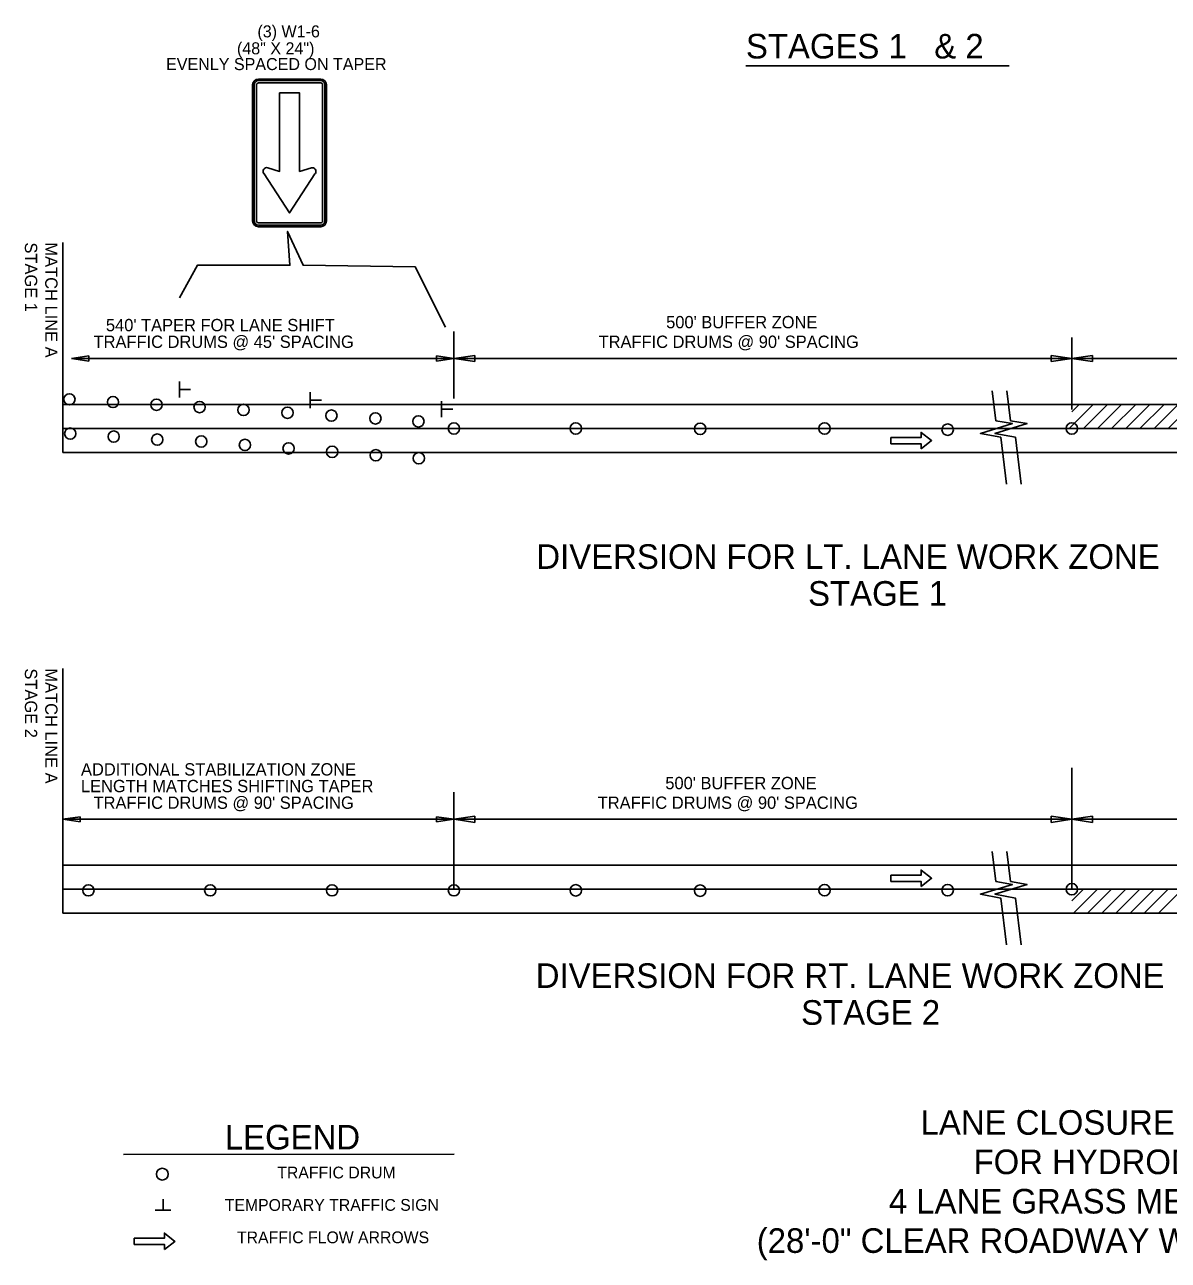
# Model space of a CAD drawing. Extents: x 1930579 to 1938222, y 596452 to 597761.
# Drawn here: x 1936678 to 1937236, y 596554 to 597157 of the extents above; entities that cross this region are included whole.
import ezdxf

# ---------------------------------------------------------------- set-up
doc = ezdxf.new("R2010")
doc.units = 0
for name, color, linetype in [('Default', 7, 'Continuous'), ('P_TC_Signs_Permanent', 7, 'Continuous'), ('R_Border', 7, 'Continuous'), ('R_MOT', 7, 'Continuous'), ('R_Striping', 7, 'Continuous')]:
    doc.layers.add(name, color=color, linetype=linetype)

msp = doc.modelspace()

# ---------------------------------------------------------------- linework, layer by layer
at = {"layer": 'Default'}
for p, q in [((1937029.73, 597136.48), (1937158.05, 597136.48)), ((1936696.54, 597050.33), (1936696.54, 596947.87)), ((1936887.3, 597006.91), (1936887.3, 596974.28)), ((1937188.67, 597003.98), (1937188.67, 596968.94)), ((1936700.72, 596993.7), (1936709.21, 596994.97)), ((1936887.3, 596993.7), (1936700.72, 596993.7)), ((1936709.21, 596992.42), (1936700.72, 596993.7)), ((1936709.21, 596994.97), (1936709.21, 596992.42)), ((1936878.81, 596992.42), (1936878.81, 596994.97)), ((1936878.81, 596994.97), (1936887.3, 596993.7)), ((1936887.3, 596993.7), (1936878.81, 596992.42)), ((1937188.67, 596993.7), (1936887.3, 596993.7)), ((1936887.38, 596993.7), (1936897.44, 596995.21)), ((1936897.44, 596992.19), (1936887.38, 596993.7)), ((1936897.44, 596995.21), (1936897.44, 596992.19)), ((1937178.61, 596992.19), (1937178.61, 596995.21)), ((1937178.61, 596995.21), (1937188.67, 596993.7)), ((1937188.67, 596993.7), (1937178.61, 596992.19)), ((1937188.67, 596993.7), (1937198.73, 596995.21)), ((1937516.16, 596993.7), (1937188.67, 596993.7)), ((1937198.73, 596992.19), (1937188.67, 596993.7)), ((1937198.73, 596995.21), (1937198.73, 596992.19)), ((1936753.38, 596974.79), (1936753.38, 596982.58)), ((1936753.49, 596978.66), (1936758.81, 596978.66)), ((1936817.26, 596969.5), (1936817.26, 596977.29)), ((1937643.39, 596971.31), (1936696.54, 596971.31)), ((1936817.37, 596973.37), (1936822.69, 596973.37)), ((1936881.28, 596965.09), (1936881.28, 596972.88)), ((1936881.4, 596968.97), (1936886.72, 596968.97)), ((1937187.39, 596959.59), (1937199.11, 596971.31)), ((1937188.67, 596967.77), (1937192.21, 596971.31)), ((1937194.3, 596959.59), (1937206.02, 596971.31)), ((1937201.21, 596959.59), (1937212.92, 596971.31)), ((1937208.11, 596959.59), (1937219.83, 596971.31)), ((1937215.02, 596959.59), (1937226.73, 596971.31)), ((1937221.92, 596959.59), (1937233.64, 596971.31)), ((1937228.83, 596959.59), (1937240.55, 596971.31)), ((1937235.73, 596959.59), (1937247.45, 596971.31)), ((1936696.54, 596959.59), (1937643.39, 596959.59)), ((1936696.54, 596947.87), (1936970.48, 596947.87)), ((1937643.39, 596947.87), (1936696.54, 596947.87)), ((1936954.98, 596947.87), (1937223.6, 596947.87)), ((1937162.33, 596947.87), (1937188.46, 596947.87)), ((1937188.46, 596947.87), (1937335.53, 596947.87)), ((1936696.54, 596842.59), (1936696.54, 596723.17)), ((1937188.67, 596794.08), (1937188.67, 596744.24)), ((1937188.67, 596794.08), (1937188.67, 596744.24)), ((1936887.3, 596782.21), (1936887.3, 596734.89)), ((1937188.67, 596782.21), (1937188.67, 596734.89)), ((1936696.54, 596769), (1936705.03, 596770.27)), ((1936887.3, 596769), (1936696.54, 596769)), ((1936705.03, 596767.72), (1936696.54, 596769)), ((1936705.03, 596770.27), (1936705.03, 596767.72)), ((1936878.81, 596767.72), (1936878.81, 596770.27)), ((1936878.81, 596770.27), (1936887.3, 596769)), ((1936887.3, 596769), (1936878.81, 596767.72)), ((1937188.67, 596769), (1936887.3, 596769)), ((1936887.38, 596769), (1936897.44, 596770.51)), ((1936897.44, 596767.49), (1936887.38, 596769)), ((1936897.44, 596770.51), (1936897.44, 596767.49)), ((1937178.61, 596767.49), (1937178.61, 596770.51)), ((1937178.61, 596770.51), (1937188.67, 596769)), ((1937188.67, 596769), (1937178.61, 596767.49)), ((1937188.67, 596769), (1937198.73, 596770.51)), ((1937516.16, 596769), (1937188.67, 596769)), ((1937198.73, 596767.49), (1937188.67, 596769)), ((1937198.73, 596770.51), (1937198.73, 596767.49)), ((1937643.39, 596746.61), (1936696.54, 596746.61)), ((1936696.54, 596734.89), (1937643.39, 596734.89)), ((1937188.67, 596729.26), (1937194.3, 596734.89)), ((1937189.49, 596723.17), (1937201.21, 596734.89)), ((1937196.39, 596723.17), (1937208.11, 596734.89)), ((1937203.3, 596723.17), (1937215.02, 596734.89)), ((1937210.2, 596723.17), (1937221.92, 596734.89)), ((1937217.11, 596723.17), (1937228.83, 596734.89)), ((1937224.01, 596723.17), (1937235.73, 596734.89)), ((1937230.92, 596723.17), (1937242.64, 596734.89)), ((1936696.54, 596723.17), (1936970.48, 596723.17)), ((1937643.39, 596723.17), (1936696.54, 596723.17)), ((1936954.98, 596723.17), (1937223.6, 596723.17)), ((1937162.33, 596723.17), (1937188.46, 596723.17)), ((1937188.46, 596723.17), (1937335.53, 596723.17))]:
    msp.add_line(p, q, dxfattribs=at)
for points in [[(1937149.85, 596978.04), (1937151.68, 596963.38), (1937159.74, 596961.96), (1937144.09, 596957.22), (1937154.05, 596955.32), (1937156.8, 596932.48)], [(1937156.96, 596978.04), (1937158.79, 596963.38), (1937166.85, 596961.96), (1937151.2, 596957.22), (1937161.16, 596955.32), (1937163.91, 596932.48)], [(1937149.85, 596753.34), (1937151.68, 596738.68), (1937159.74, 596737.26), (1937144.09, 596732.52), (1937154.05, 596730.62), (1937156.8, 596707.78)], [(1937156.96, 596753.34), (1937158.79, 596738.68), (1937166.85, 596737.26), (1937151.2, 596732.52), (1937161.16, 596730.62), (1937163.91, 596707.78)]]:
    msp.add_lwpolyline(points, dxfattribs=at)
for centre, radius in [((1936699.79, 596973.82), 2.75), ((1936721.02, 596972.51), 2.75), ((1936742.25, 596971.19), 2.75), ((1936763.24, 596970.03), 2.75), ((1936784.68, 596968.65), 2.75), ((1936806.12, 596967.26), 2.75), ((1936827.55, 596965.88), 2.75), ((1936848.99, 596964.5), 2.75), ((1936869.99, 596963.06), 2.75), ((1936887.3, 596959.59), 2.75), ((1936946.73, 596959.59), 2.8), ((1937007.41, 596959.44), 2.8), ((1937068.09, 596959.59), 2.8), ((1937128.13, 596959.01), 2.8), ((1937188.67, 596959.59), 2.8), ((1936700.15, 596957.12), 2.75), ((1936721.36, 596955.65), 2.75), ((1936742.58, 596954.17), 2.75), ((1936764.09, 596953.25), 2.75), ((1936785.37, 596951.58), 2.75), ((1936806.65, 596949.9), 2.75), ((1936827.93, 596948.22), 2.75), ((1936849.21, 596946.54), 2.75), ((1936870.19, 596945.08), 2.75), ((1936709.01, 596734.35), 2.75), ((1936768.44, 596734.35), 2.75), ((1936827.87, 596734.35), 2.75), ((1936887.3, 596734.35), 2.75), ((1936946.73, 596734.35), 2.8), ((1937007.41, 596734.21), 2.8), ((1937068.09, 596734.41), 2.8), ((1937128.13, 596734.42), 2.8), ((1937188.67, 596734.89), 2.8), ((1936745.07, 596595.94), 2.88)]:
    msp.add_circle(centre, radius, dxfattribs=at)
at = {"layer": 'P_TC_Signs_Permanent'}
for p, q in [((1936789.13, 597127.18), (1936789.13, 597060.81)), ((1936789.88, 597127.18), (1936789.88, 597060.81)), ((1936791.01, 597127.18), (1936791.01, 597060.81)), ((1936822.32, 597129.99), (1936791.95, 597129.99)), ((1936822.32, 597129.24), (1936791.95, 597129.24)), ((1936822.32, 597128.12), (1936791.95, 597128.12)), ((1936823.26, 597060.81), (1936823.26, 597127.18)), ((1936824.38, 597060.81), (1936824.38, 597127.18)), ((1936825.13, 597060.81), (1936825.13, 597127.18)), ((1936791.95, 597059.87), (1936822.32, 597059.87)), ((1936791.95, 597058.74), (1936822.32, 597058.74)), ((1936791.95, 597057.99), (1936822.32, 597057.99))]:
    msp.add_line(p, q, dxfattribs=at)
for points in [[(1936817.77, 597086.7), (1936812.01, 597084.98), (1936812.01, 597123.24), (1936802.26, 597123.24), (1936802.26, 597084.98), (1936796.51, 597086.73)], [(1936794.69, 597083.74), (1936807.13, 597064.74), (1936819.54, 597083.75)]]:
    msp.add_lwpolyline(points, dxfattribs=at)
for centre, radius, start, end in [((1936791.95, 597127.18), 2.81, 90, 180), ((1936791.95, 597127.18), 2.06, 90, 180), ((1936791.95, 597127.18), 0.938, 90, 180), ((1936822.32, 597127.18), 2.81, 360, 90), ((1936822.32, 597127.18), 2.06, 360, 90), ((1936822.32, 597127.18), 0.937, 360, 90), ((1936796.02, 597085), 1.8, 74.03093, 213.47548), ((1936731.96, 597042.64), 75, 33.2286, 33.47548), ((1936818.25, 597085), 1.76, 326.59943, 105.96908), ((1936882.34, 597042.74), 75, 146.59943, 146.85697), ((1936791.95, 597060.81), 2.81, 180, 270), ((1936791.95, 597060.81), 2.06, 180, 270), ((1936791.95, 597060.81), 0.938, 180, 270), ((1936822.32, 597060.81), 2.81, 270, 360), ((1936822.32, 597060.81), 2.06, 270, 360), ((1936822.32, 597060.81), 0.938, 270, 360)]:
    msp.add_arc(centre, radius, start, end, dxfattribs=at)
at = {"layer": 'R_Border'}
for p, q in [((1936726.09, 596605.58), (1936887.49, 596605.69)), ((1936745.44, 596578.5), (1936745.44, 596583.74)), ((1936749.26, 596578.39), (1936741.58, 596578.39))]:
    msp.add_line(p, q, dxfattribs=at)
msp.add_lwpolyline([(1936753.38, 597023.29), (1936762.17, 597039.21), (1936807.32, 597039.21), (1936806.15, 597055.7), (1936813.77, 597039.21), (1936868.47, 597038.42), (1936883.18, 597008.99)], dxfattribs=at)
at = {"layer": 'R_MOT'}
msp.add_lwpolyline([(1936746.07, 596559.17), (1936751.26, 596563.18), (1936746.07, 596567.17), (1936746.07, 596564.67), (1936731.36, 596564.66), (1936731.36, 596561.66), (1936746.07, 596561.67)], close=True, dxfattribs=at)
at = {"layer": 'R_Striping'}
for points in [[(1937115.13, 596949.68), (1937120.32, 596953.68), (1937115.13, 596957.68), (1937115.13, 596955.18), (1937100.41, 596955.18), (1937100.41, 596952.18), (1937115.13, 596952.18)], [(1937115.13, 596736.23), (1937120.32, 596740.23), (1937115.13, 596744.23), (1937115.13, 596741.73), (1937100.41, 596741.73), (1937100.41, 596738.73), (1937115.13, 596738.73)]]:
    msp.add_lwpolyline(points, close=True, dxfattribs=at)

# ---------------------------------------------------------------- texts
at = {"layer": 'Default'}
for s, height, rotation, p in [('STAGES 1   & 2', 12, 360, (1937029.73, 597140.05)), ('STAGE 1', 6, 270, (1936678.04, 597050.33)), ('MATCH LINE A ', 6, 270, (1936687.95, 597050.33)), ("540' TAPER FOR LANE SHIFT", 6, 360, (1936717.57, 597007.03)), ("500' BUFFER ZONE", 6, 360, (1936990.82, 597008.47)), ("TRAFFIC DRUMS @ 45' SPACING", 6, 360, (1936711.54, 596998.9)), ("TRAFFIC DRUMS @ 90' SPACING", 6, 360, (1936957.86, 596998.9)), ('DIVERSION FOR LT. LANE WORK ZONE', 12, 360, (1936927.5, 596891.14)), ('STAGE 1', 12, 360, (1937060.06, 596873.16)), ('STAGE 2', 6, 270, (1936678.04, 596842.59)), ('MATCH LINE A ', 6, 270, (1936687.95, 596842.59)), ('ADDITIONAL STABILIZATION ZONE', 6, 360, (1936705.41, 596790.36)), ('LENGTH MATCHES SHIFTING TAPER', 6, 360, (1936705.38, 596782.23)), ("500' BUFFER ZONE", 6, 360, (1936990.42, 596783.68)), ("TRAFFIC DRUMS @ 90' SPACING", 6, 360, (1936711.54, 596774.11)), ("TRAFFIC DRUMS @ 90' SPACING", 6, 360, (1936957.45, 596774.11)), ('DIVERSION FOR RT. LANE WORK ZONE', 12, 360, (1936927.21, 596686.77)), ('STAGE 2', 12, 360, (1937056.66, 596668.8)), ('LANE CLOSURE WITH TRAFFIC DRUMS', 12, 360, (1937114.93, 596615.15)), ('FOR HYDRODEMOLITION BRIDGES ', 12, 360, (1937140.73, 596595.95)), ('4 LANE GRASS MEDIAN DIVIDED HIGHWAY', 12, 360, (1937099.44, 596576.75)), ('(28\'-0" CLEAR ROADWAY WIDTH ON THE BRIDGE DECK)', 12, 360, (1937035, 596557.55))]:
    msp.add_text(s, height=height, rotation=rotation, dxfattribs=at).set_placement(p)
at = {"layer": 'R_Border'}
for s, height, rotation, p in [('(3) W1-6', 5.859, 0.00754, (1936791.46, 597150.34)), ('(48" X 24")', 5.8594, 0.00754, (1936781.48, 597142.07)), ('EVENLY SPACED ON TAPER', 5.8594, 0.00754, (1936746.9, 597134.38)), ('LEGEND', 12, 0.03878, (1936775.57, 596607.95)), ('TRAFFIC DRUM', 5.76, 0.03876, (1936801.15, 596593.84)), ('TEMPORARY TRAFFIC SIGN', 5.76, 0.03876, (1936775.54, 596578.01)), ('TRAFFIC FLOW ARROWS', 5.76, 0.03876, (1936781.5, 596562.21))]:
    msp.add_text(s, height=height, rotation=rotation, dxfattribs=at).set_placement(p)

doc.saveas('drawing.dxf')
